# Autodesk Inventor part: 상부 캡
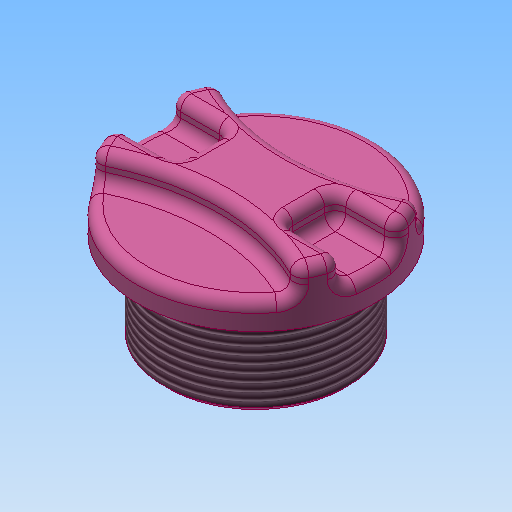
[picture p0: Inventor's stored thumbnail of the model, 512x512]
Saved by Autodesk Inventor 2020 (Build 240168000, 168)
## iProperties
Created: 2016-09
Part Number: 상부 캡
Material: ABS 플라스틱
Document SubType Name: Modeling
Designer: mduedu
Density: 1.06 g/cm^3
Appearance: 분홍색
Author: mduedu
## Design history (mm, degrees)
sketch "스케치1"
  geometry: C1 r 22.5 at (0, 0); 1 further point
  constraints: 1 centre point, 1 coincident
  dimensions: "d0" = 45 diameter of C1
extrude "돌출1" new body sketch "스케치1" distance "d1" = 10; taper "d2" = 0 deg
sketch "스케치2" dims "d4" = 80
  geometry: C1 r 22.5 at (0, 0) reference; 3 further points
  constraints: 3 vertical alignment, 2 other
  dimensions: "d3" = 7 distance of point (0, 7) point (0, 0)
extrude "돌출2" cut sketch "스케치2" distance "d5" = 5; taper "d6" = 0 deg
sketch "스케치3"
  geometry: L1 (-22.5, 0)-(0, 0); L2 (-21.937, 5)-(-10, 5); L3 (-10, 5)-(-10, -5); L4 (-10, -5)-(-21.937, -5); A1 r 22.5 centre (0, 0) between (-19.118, 11.864) and (-19.118, -11.864) reference; A2 r 22.5 centre (0, 0) between (-21.937, 5) and (-21.937, -5); 1 further point
  constraints: 8 end point, 5 point on circle, 2 horizontal, 1 centre point, 1 coincident, 1 parallel, 1 perpendicular, 1 symmetric about line
  dimensions: "d7" = 10 distance from line of L3 point (0, 0); "d8" = 10 distance of L2.end L3.end
extrude "돌출3" cut sketch "스케치3" distance "d9" = 5; taper "d10" = 0 deg
fillet "모깎기1" dims "d11" = 2
fillet "모깎기2" dims "d12" = 2
fillet "모깎기3" dims "d13" = 2
sketch "스케치4"
  geometry: C1 r 17.5 at (0, 0); 1 further point
  constraints: 1 centre point, 1 coincident
  dimensions: "d14" = 35 diameter of C1
extrude "돌출4" join sketch "스케치4" distance "d15" = 17; taper "d16" = 0 deg
sketch "스케치5"
  geometry: C1 r 12.5 at (0, 0); 1 further point
  constraints: 1 centre point, 1 coincident
  dimensions: "d17" = 25 diameter of C1
extrude "돌출5" cut sketch "스케치5" distance "d18" = 10; taper "d19" = 0 deg
fillet "모깎기4" dims "d20" = 3
feature "스레드1" dims "d21" = 10, "d22" = 0
chamfer "모따기1" distance "d23" = 1; stored, may be unused: second distance "d24" = 2, angle "d25" = 45 deg
node "솔리드1"
mirror "대칭1"
mirror "대칭2"
node "투영된 루프1"
